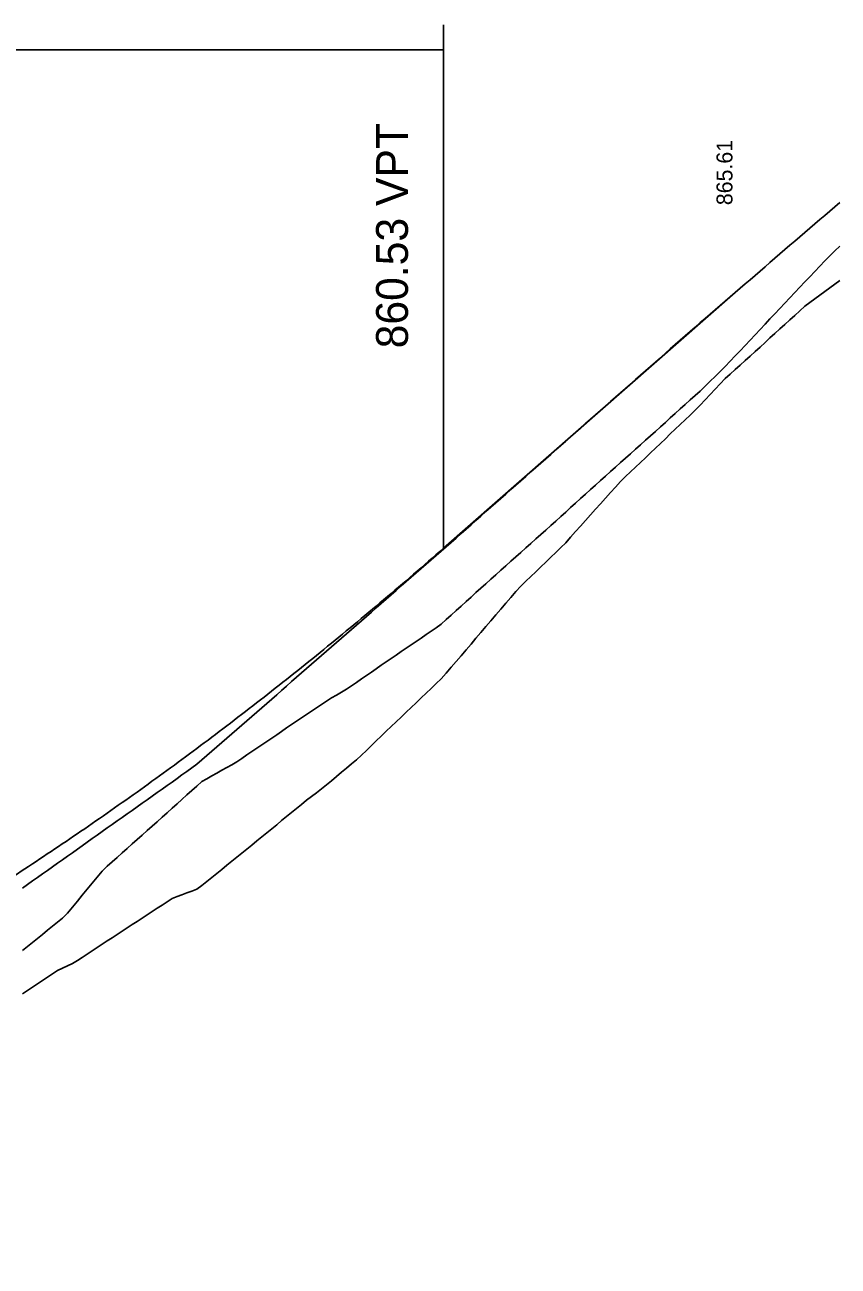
# Model space of a CAD drawing. Extents: x 1733669 to 1739080, y 1214897 to 1219897.
# Drawn here: x 1735487.8 to 1735651, y 1217858.1 to 1218107.1 of the extents above; entities that cross this region are included whole.
import ezdxf

# ---------------------------------------------------------------- set-up
doc = ezdxf.new("R2010")
doc.units = 0
for name, color, linetype in [('RD_DDB_Profile_EX', 7, 'Continuous'), ('RD_DDB_Profile_Lbl', 7, 'Continuous'), ('RD_DDB_Profile_PR', 7, 'Continuous'), ('RD_DDB_StripGrade', 7, 'Continuous'), ('RD_DDB_VCLbl', 7, 'Continuous'), ('RD_Sketch1', 7, 'Continuous'), ('RD_Sketch2', 7, 'Continuous')]:
    doc.layers.add(name, color=color, linetype=linetype)

msp = doc.modelspace()

# ---------------------------------------------------------------- linework, layer by layer
at = {"layer": 'RD_DDB_Profile_EX'}
for points in [[(1735583.3, 1218012.08), (1735584.3, 1218012.96), (1735585.3, 1218013.85), (1735586.3, 1218014.73), (1735587.3, 1218015.61), (1735588.3, 1218016.5), (1735589.3, 1218017.38), (1735590.3, 1218018.26), (1735591.3, 1218019.15), (1735592.3, 1218020.03), (1735593.3, 1218020.91), (1735594.3, 1218021.79), (1735595.3, 1218022.68), (1735596.3, 1218023.56), (1735597.3, 1218024.43), (1735598.3, 1218025.31), (1735599.3, 1218026.19), (1735600.3, 1218027.08), (1735601.3, 1218027.96), (1735602.3, 1218028.84), (1735603.3, 1218029.72), (1735604.3, 1218030.61), (1735605.3, 1218031.49), (1735606.3, 1218032.37), (1735607.3, 1218033.25), (1735608.3, 1218034.14), (1735609.3, 1218035.02), (1735610.3, 1218035.9), (1735611.3, 1218036.78), (1735612.3, 1218037.67), (1735613.3, 1218038.55), (1735614.3, 1218039.43), (1735615.3, 1218040.31), (1735616.3, 1218041.2), (1735617.3, 1218042.08), (1735618.3, 1218042.96), (1735619.3, 1218043.84), (1735620.3, 1218044.72), (1735621.3, 1218045.59), (1735622.3, 1218046.46), (1735623.3, 1218047.34), (1735624.3, 1218048.2), (1735625.3, 1218049.06), (1735626.3, 1218049.92), (1735627.3, 1218050.78), (1735628.3, 1218051.64), (1735629.3, 1218052.51), (1735630.3, 1218053.37), (1735631.3, 1218054.23), (1735632.3, 1218055.09), (1735633.3, 1218055.95), (1735634.3, 1218056.82), (1735635.3, 1218057.68), (1735636.3, 1218058.54), (1735637.3, 1218059.4), (1735638.3, 1218060.26), (1735639.3, 1218061.12), (1735640.3, 1218061.99), (1735641.3, 1218062.85), (1735642.3, 1218063.71), (1735643.3, 1218064.57), (1735644.3, 1218065.43), (1735645.3, 1218066.29), (1735646.3, 1218067.16), (1735647.3, 1218068), (1735648.3, 1218068.86), (1735649.3, 1218069.72), (1735650.3, 1218070.58), (1735651.3, 1218071.44)], [(1735487.3, 1217933.93), (1735488.3, 1217934.64), (1735489.3, 1217935.34), (1735490.3, 1217936.05), (1735491.3, 1217936.76), (1735492.3, 1217937.47), (1735493.3, 1217938.18), (1735494.3, 1217938.89), (1735495.3, 1217939.6), (1735496.3, 1217940.3), (1735497.3, 1217941.01), (1735498.3, 1217941.72), (1735499.3, 1217942.42), (1735500.3, 1217943.13), (1735501.3, 1217943.84), (1735502.3, 1217944.55), (1735503.3, 1217945.26), (1735504.3, 1217945.97), (1735505.3, 1217946.68), (1735506.3, 1217947.39), (1735507.3, 1217948.09), (1735508.3, 1217948.8), (1735509.3, 1217949.51), (1735510.3, 1217950.22), (1735511.3, 1217950.93), (1735512.3, 1217951.64), (1735513.3, 1217952.35), (1735514.3, 1217953.06), (1735515.3, 1217953.77), (1735516.3, 1217954.47), (1735517.3, 1217955.18), (1735518.3, 1217955.89), (1735519.3, 1217956.6), (1735520.3, 1217957.31), (1735521.3, 1217958.02), (1735522.3, 1217958.74), (1735523.3, 1217959.61), (1735524.3, 1217960.49), (1735525.3, 1217961.36), (1735526.3, 1217962.23), (1735527.3, 1217963.1), (1735528.3, 1217963.98), (1735529.3, 1217964.85), (1735530.3, 1217965.72), (1735531.3, 1217966.59), (1735532.3, 1217967.47), (1735533.3, 1217968.34), (1735534.3, 1217969.21), (1735535.3, 1217970.08), (1735536.3, 1217970.96), (1735537.3, 1217971.83), (1735538.3, 1217972.7), (1735539.3, 1217973.57), (1735540.3, 1217974.45), (1735541.3, 1217975.32), (1735542.3, 1217976.19), (1735543.3, 1217977.06), (1735544.3, 1217977.93), (1735545.3, 1217978.81), (1735546.3, 1217979.68), (1735547.3, 1217980.55), (1735548.3, 1217981.43), (1735549.3, 1217982.3), (1735550.3, 1217983.17), (1735551.3, 1217984.04), (1735552.3, 1217984.92), (1735553.3, 1217985.79), (1735554.3, 1217986.66), (1735555.3, 1217987.53), (1735556.3, 1217988.41), (1735557.3, 1217989.28), (1735558.3, 1217990.15), (1735559.3, 1217991.02), (1735560.3, 1217991.9), (1735561.3, 1217992.77), (1735562.3, 1217993.64), (1735563.3, 1217994.51), (1735564.3, 1217995.39), (1735565.3, 1217996.26), (1735566.3, 1217997.13), (1735567.3, 1217998), (1735568.3, 1217998.88), (1735569.3, 1217999.75), (1735570.3, 1218000.62), (1735571.3, 1218001.49), (1735572.3, 1218002.37), (1735573.3, 1218003.25), (1735574.3, 1218004.13), (1735575.3, 1218005.02), (1735576.3, 1218005.9), (1735577.3, 1218006.78), (1735578.3, 1218007.67), (1735579.3, 1218008.55), (1735580.3, 1218009.43), (1735581.3, 1218010.32), (1735582.3, 1218011.2), (1735583.3, 1218012.08)]]:
    msp.add_lwpolyline(points, dxfattribs=at)
at = {"layer": 'RD_DDB_Profile_PR'}
msp.add_line((1735571.77, 1218002.08), (1735629.77, 1218052.9), dxfattribs=at)
msp.add_spline([(1735271.77, 1217858.07), (1735277.77, 1217858.62), (1735283.77, 1217859.27), (1735289.77, 1217860.01), (1735295.77, 1217860.84), (1735301.77, 1217861.77), (1735307.77, 1217862.8), (1735313.77, 1217863.92), (1735319.77, 1217865.13), (1735325.77, 1217866.44), (1735331.77, 1217867.85), (1735337.77, 1217869.35), (1735343.77, 1217870.95), (1735349.77, 1217872.64), (1735355.77, 1217874.42), (1735361.77, 1217876.3), (1735367.77, 1217878.28), (1735373.77, 1217880.35), (1735379.77, 1217882.52), (1735385.77, 1217884.78), (1735391.77, 1217887.14), (1735397.77, 1217889.59), (1735403.77, 1217892.14), (1735409.77, 1217894.78), (1735415.77, 1217897.52), (1735421.77, 1217900.35), (1735427.77, 1217903.28), (1735433.77, 1217906.3), (1735439.77, 1217909.42), (1735445.77, 1217912.63), (1735451.77, 1217915.94), (1735457.77, 1217919.34), (1735463.77, 1217922.84), (1735469.77, 1217926.43), (1735475.77, 1217930.12), (1735481.77, 1217933.91), (1735487.77, 1217937.78), (1735493.77, 1217941.76), (1735499.77, 1217945.83), (1735505.77, 1217949.99), (1735511.77, 1217954.25), (1735517.77, 1217958.6), (1735523.77, 1217963.05), (1735529.77, 1217967.6), (1735535.77, 1217972.24), (1735541.77, 1217976.97), (1735547.77, 1217981.8), (1735553.77, 1217986.73), (1735559.77, 1217991.75), (1735565.77, 1217996.86), (1735571.77, 1218002.08)], degree=3, dxfattribs=at)
at = {"layer": 'RD_DDB_VCLbl'}
for p, q in [((1735571.77, 1218107.08), (1735571.77, 1218002.08)), ((1735271.77, 1218102.08), (1735571.77, 1218102.08))]:
    msp.add_line(p, q, dxfattribs=at)
at = {"layer": 'RD_Sketch1'}
for points in [[(1735583.3, 1217989.87), (1735584.3, 1217991.04), (1735585.3, 1217992.21), (1735586.3, 1217993.38), (1735587.3, 1217994.48), (1735588.3, 1217995.45), (1735589.3, 1217996.42), (1735590.3, 1217997.38), (1735591.3, 1217998.35), (1735592.3, 1217999.32), (1735593.3, 1218000.29), (1735594.3, 1218001.26), (1735595.3, 1218002.22), (1735596.3, 1218003.19), (1735597.3, 1218004.3), (1735598.3, 1218005.42), (1735599.3, 1218006.54), (1735600.3, 1218007.66), (1735601.3, 1218008.77), (1735602.3, 1218009.89), (1735603.3, 1218011.01), (1735604.3, 1218012.13), (1735605.3, 1218013.24), (1735606.3, 1218014.36), (1735607.3, 1218015.48), (1735608.3, 1218016.46), (1735609.3, 1218017.41), (1735610.3, 1218018.36), (1735611.3, 1218019.3), (1735612.3, 1218020.25), (1735613.3, 1218021.2), (1735614.3, 1218022.15), (1735615.3, 1218023.1), (1735616.3, 1218024.05), (1735617.3, 1218025), (1735618.3, 1218025.95), (1735619.3, 1218026.9), (1735620.3, 1218027.85), (1735621.3, 1218028.8), (1735622.3, 1218029.75), (1735623.3, 1218030.75), (1735624.3, 1218031.82), (1735625.3, 1218032.9), (1735626.3, 1218033.98), (1735627.3, 1218035.05), (1735628.3, 1218036.1), (1735629.3, 1218037.01), (1735630.3, 1218037.92), (1735631.3, 1218038.82), (1735632.3, 1218039.73), (1735633.3, 1218040.64), (1735634.3, 1218041.54), (1735635.3, 1218042.45), (1735636.3, 1218043.36), (1735637.3, 1218044.27), (1735638.3, 1218045.17), (1735639.3, 1218046.08), (1735640.3, 1218046.99), (1735641.3, 1218047.89), (1735642.3, 1218048.8), (1735643.3, 1218049.71), (1735644.3, 1218050.61), (1735645.3, 1218051.35), (1735646.3, 1218052.09), (1735647.3, 1218052.83), (1735648.3, 1218053.57), (1735649.3, 1218054.31), (1735650.3, 1218055.05), (1735651.3, 1218055.79)], [(1735487.3, 1217912.73), (1735488.3, 1217913.39), (1735489.3, 1217914.06), (1735490.3, 1217914.72), (1735491.3, 1217915.39), (1735492.3, 1217916.05), (1735493.3, 1217916.71), (1735494.3, 1217917.37), (1735495.3, 1217917.84), (1735496.3, 1217918.32), (1735497.3, 1217918.8), (1735498.3, 1217919.36), (1735499.3, 1217920.01), (1735500.3, 1217920.67), (1735501.3, 1217921.33), (1735502.3, 1217921.98), (1735503.3, 1217922.64), (1735504.3, 1217923.3), (1735505.3, 1217923.95), (1735506.3, 1217924.61), (1735507.3, 1217925.27), (1735508.3, 1217925.92), (1735509.3, 1217926.58), (1735510.3, 1217927.24), (1735511.3, 1217927.89), (1735512.3, 1217928.55), (1735513.3, 1217929.21), (1735514.3, 1217929.87), (1735515.3, 1217930.52), (1735516.3, 1217931.18), (1735517.3, 1217931.83), (1735518.3, 1217932.2), (1735519.3, 1217932.56), (1735520.3, 1217932.93), (1735521.3, 1217933.29), (1735522.3, 1217933.67), (1735523.3, 1217934.41), (1735524.3, 1217935.22), (1735525.3, 1217936.04), (1735526.3, 1217936.85), (1735527.3, 1217937.66), (1735528.3, 1217938.48), (1735529.3, 1217939.29), (1735530.3, 1217940.11), (1735531.3, 1217940.92), (1735532.3, 1217941.74), (1735533.3, 1217942.55), (1735534.3, 1217943.37), (1735535.3, 1217944.18), (1735536.3, 1217945), (1735537.3, 1217945.81), (1735538.3, 1217946.63), (1735539.3, 1217947.44), (1735540.3, 1217948.26), (1735541.3, 1217949.07), (1735542.3, 1217949.89), (1735543.3, 1217950.7), (1735544.3, 1217951.52), (1735545.3, 1217952.29), (1735546.3, 1217953.04), (1735547.3, 1217953.79), (1735548.3, 1217954.62), (1735549.3, 1217955.46), (1735550.3, 1217956.3), (1735551.3, 1217957.14), (1735552.3, 1217957.98), (1735553.3, 1217958.82), (1735554.3, 1217959.66), (1735555.3, 1217960.58), (1735556.3, 1217961.53), (1735557.3, 1217962.49), (1735558.3, 1217963.44), (1735559.3, 1217964.4), (1735560.3, 1217965.36), (1735561.3, 1217966.31), (1735562.3, 1217967.27), (1735563.3, 1217968.23), (1735564.3, 1217969.18), (1735565.3, 1217970.14), (1735566.3, 1217971.1), (1735567.3, 1217972.05), (1735568.3, 1217973.01), (1735569.3, 1217973.97), (1735570.3, 1217974.92), (1735571.3, 1217975.88), (1735572.3, 1217977.03), (1735573.3, 1217978.2), (1735574.3, 1217979.37), (1735575.3, 1217980.53), (1735576.3, 1217981.7), (1735577.3, 1217982.87), (1735578.3, 1217984.04), (1735579.3, 1217985.2), (1735580.3, 1217986.37), (1735581.3, 1217987.54), (1735582.3, 1217988.71), (1735583.3, 1217989.87)]]:
    msp.add_lwpolyline(points, dxfattribs=at)
at = {"layer": 'RD_Sketch2'}
for points in [[(1735583.3, 1217997.66), (1735584.3, 1217998.56), (1735585.3, 1217999.46), (1735586.3, 1218000.35), (1735587.3, 1218001.25), (1735588.3, 1218002.15), (1735589.3, 1218003.05), (1735590.3, 1218003.94), (1735591.3, 1218004.84), (1735592.3, 1218005.74), (1735593.3, 1218006.63), (1735594.3, 1218007.53), (1735595.3, 1218008.43), (1735596.3, 1218009.33), (1735597.3, 1218010.24), (1735598.3, 1218011.15), (1735599.3, 1218012.06), (1735600.3, 1218012.96), (1735601.3, 1218013.86), (1735602.3, 1218014.76), (1735603.3, 1218015.65), (1735604.3, 1218016.55), (1735605.3, 1218017.45), (1735606.3, 1218018.35), (1735607.3, 1218019.25), (1735608.3, 1218020.14), (1735609.3, 1218021.04), (1735610.3, 1218021.94), (1735611.3, 1218022.84), (1735612.3, 1218023.73), (1735613.3, 1218024.63), (1735614.3, 1218025.53), (1735615.3, 1218026.43), (1735616.3, 1218027.32), (1735617.3, 1218028.22), (1735618.3, 1218029.12), (1735619.3, 1218030.02), (1735620.3, 1218030.91), (1735621.3, 1218031.82), (1735622.3, 1218032.72), (1735623.3, 1218033.61), (1735624.3, 1218034.59), (1735625.3, 1218035.57), (1735626.3, 1218036.56), (1735627.3, 1218037.55), (1735628.3, 1218038.53), (1735629.3, 1218039.59), (1735630.3, 1218040.65), (1735631.3, 1218041.71), (1735632.3, 1218042.77), (1735633.3, 1218043.83), (1735634.3, 1218044.89), (1735635.3, 1218045.95), (1735636.3, 1218047.01), (1735637.3, 1218048.07), (1735638.3, 1218049.13), (1735639.3, 1218050.19), (1735640.3, 1218051.25), (1735641.3, 1218052.31), (1735642.3, 1218053.37), (1735643.3, 1218054.43), (1735644.3, 1218055.49), (1735645.3, 1218056.55), (1735646.3, 1218057.61), (1735647.3, 1218058.67), (1735648.3, 1218059.72), (1735649.3, 1218060.72), (1735650.3, 1218061.71), (1735651.3, 1218062.7)], [(1735487.3, 1217921.39), (1735488.3, 1217922.2), (1735489.3, 1217923.01), (1735490.3, 1217923.82), (1735491.3, 1217924.63), (1735492.3, 1217925.44), (1735493.3, 1217926.25), (1735494.3, 1217927.06), (1735495.3, 1217927.87), (1735496.3, 1217928.9), (1735497.3, 1217930.1), (1735498.3, 1217931.3), (1735499.3, 1217932.51), (1735500.3, 1217933.71), (1735501.3, 1217934.91), (1735502.3, 1217936.11), (1735503.3, 1217937.32), (1735504.3, 1217938.29), (1735505.3, 1217939.18), (1735506.3, 1217940.08), (1735507.3, 1217940.97), (1735508.3, 1217941.86), (1735509.3, 1217942.76), (1735510.3, 1217943.65), (1735511.3, 1217944.55), (1735512.3, 1217945.44), (1735513.3, 1217946.34), (1735514.3, 1217947.23), (1735515.3, 1217948.13), (1735516.3, 1217949.02), (1735517.3, 1217949.92), (1735518.3, 1217950.81), (1735519.3, 1217951.7), (1735520.3, 1217952.6), (1735521.3, 1217953.49), (1735522.3, 1217954.39), (1735523.3, 1217955.27), (1735524.3, 1217955.83), (1735525.3, 1217956.4), (1735526.3, 1217956.97), (1735527.3, 1217957.54), (1735528.3, 1217958.11), (1735529.3, 1217958.67), (1735530.3, 1217959.25), (1735531.3, 1217959.93), (1735532.3, 1217960.61), (1735533.3, 1217961.29), (1735534.3, 1217961.96), (1735535.3, 1217962.64), (1735536.3, 1217963.32), (1735537.3, 1217963.99), (1735538.3, 1217964.67), (1735539.3, 1217965.35), (1735540.3, 1217966.03), (1735541.3, 1217966.7), (1735542.3, 1217967.38), (1735543.3, 1217968.06), (1735544.3, 1217968.73), (1735545.3, 1217969.41), (1735546.3, 1217970.09), (1735547.3, 1217970.77), (1735548.3, 1217971.44), (1735549.3, 1217972.05), (1735550.3, 1217972.64), (1735551.3, 1217973.23), (1735552.3, 1217973.82), (1735553.3, 1217974.49), (1735554.3, 1217975.18), (1735555.3, 1217975.86), (1735556.3, 1217976.55), (1735557.3, 1217977.23), (1735558.3, 1217977.92), (1735559.3, 1217978.6), (1735560.3, 1217979.28), (1735561.3, 1217979.97), (1735562.3, 1217980.65), (1735563.3, 1217981.34), (1735564.3, 1217982.02), (1735565.3, 1217982.71), (1735566.3, 1217983.39), (1735567.3, 1217984.07), (1735568.3, 1217984.76), (1735569.3, 1217985.44), (1735570.3, 1217986.13), (1735571.3, 1217986.87), (1735572.3, 1217987.78), (1735573.3, 1217988.68), (1735574.3, 1217989.59), (1735575.3, 1217990.48), (1735576.3, 1217991.38), (1735577.3, 1217992.28), (1735578.3, 1217993.18), (1735579.3, 1217994.07), (1735580.3, 1217994.97), (1735581.3, 1217995.87), (1735582.3, 1217996.77), (1735583.3, 1217997.66)]]:
    msp.add_lwpolyline(points, dxfattribs=at)

# ---------------------------------------------------------------- texts
at = {"layer": 'RD_DDB_Profile_Lbl'}
msp.add_text('865.61', height=3.2, rotation=90, dxfattribs=at).set_placement((1735629.77, 1218070.9))
at = {"layer": 'RD_DDB_StripGrade'}
msp.add_text('860.53 VPT', height=6.4, rotation=90, dxfattribs=at).set_placement((1735564.65, 1218042.18))

doc.saveas('drawing.dxf')
